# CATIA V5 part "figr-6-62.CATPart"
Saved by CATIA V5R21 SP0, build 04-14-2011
Part number: Part1
Bounding box of the stored display mesh (mm): x -50.648 to 50.648, y -72.183 to 72.183, z -40 to 40
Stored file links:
  D:\CATIA V5R21 E-RESOURCES\CATIA-V5R21\catia-v5r21-prt\c06-catia-v5r21-prt\c06-catia-v5r21-figr-6-62.CATPart
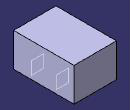
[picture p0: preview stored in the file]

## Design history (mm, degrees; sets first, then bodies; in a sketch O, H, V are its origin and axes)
Set1
  Plane1: type Offset, RefPlane face of Pad1, Offset -50, reversed
  Plane2: type Offset, RefPlane Plane1, Offset 53
Body1 (main body)
  Sketch1 on xy-plane, origin (0, 0, 0), H (1, 0, 0), V (0, 1, 0)
    line L1 (-50.6478, 72.1832) -> (50.6478, 72.1832)
    line L2 (50.6478, 72.1832) -> (50.6478, -72.1832)
    line L3 (50.6478, -72.1832) -> (-50.6478, -72.1832)
    line L4 (-50.6478, -72.1832) -> (-50.6478, 72.1832)
    axis line L5 (50.6478, -72.1832) -> (-50.6478, 72.1832)
    horizontal: L1 H, L3 H
    vertical: L2 V, L4 V
    midpoint: O L5
  Pad1: profile Sketch1, direction (0, 0, 1), length 40, mirrored extent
